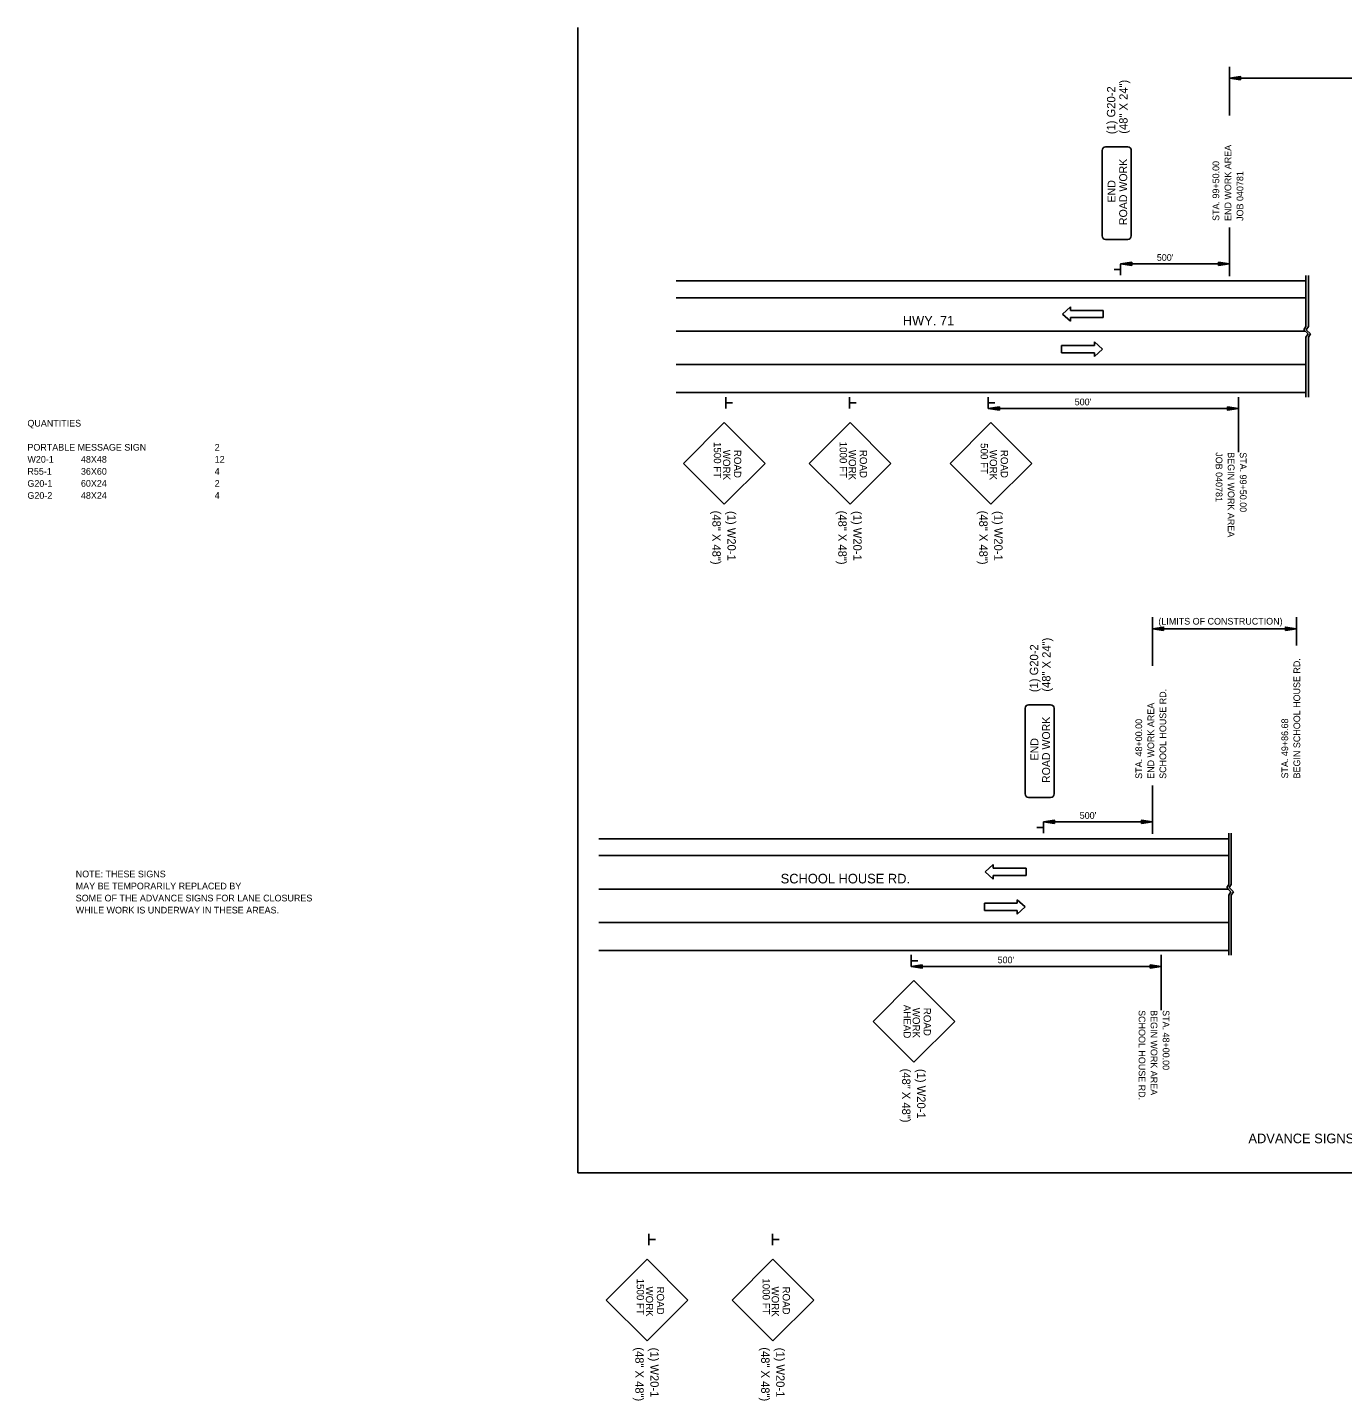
# Model space of a CAD drawing. Extents: x -900 to 1835992, y -12334 to 301063.
# Drawn here: x -900.1 to -428.3, y -12334.1 to -11841.5 of the extents above; entities that cross this region are included whole.
import ezdxf

# ---------------------------------------------------------------- set-up
doc = ezdxf.new("R2010")
doc.units = 0
for name, color, linetype in [('1', 7, 'Continuous'), ('Level 1', 7, 'Continuous'), ('R_MOT', 7, 'Continuous')]:
    doc.layers.add(name, color=color, linetype=linetype)

msp = doc.modelspace()

# ---------------------------------------------------------------- linework, layer by layer
at = {"layer": '1'}
for p, q in [((-468.81, -11873.11), (-468.81, -11855.67)), ((-468.81, -11855.67), (-468.81, -11860.92)), ((-322.23, -11859.76), (-468.81, -11859.76)), ((-468.81, -11930.7), (-468.81, -11913.26)), ((-507.89, -11928.41), (-510.26, -11928.41)), ((-468.81, -11926.36), (-507.89, -11926.36)), ((-507.89, -11926.38), (-507.89, -11930.44)), ((-441.41, -11948.8), (-441.41, -11930.46)), ((-440.54, -11948.8), (-440.54, -11930.46)), ((-667.41, -11932.46), (-441.41, -11932.46)), ((-667.41, -11938.46), (-441.41, -11938.46)), ((-667.41, -11950.46), (-441.67, -11950.46)), ((-441.41, -11948.8), (-442.18, -11949.95)), ((-442.18, -11949.95), (-440.65, -11951.48)), ((-440.54, -11948.8), (-441.31, -11949.95)), ((-441.31, -11949.95), (-439.78, -11951.48)), ((-440.65, -11951.48), (-441.41, -11952.62)), ((-441.41, -11974.2), (-441.41, -11952.62)), ((-439.78, -11951.48), (-440.54, -11952.62)), ((-440.54, -11974.2), (-440.54, -11952.62)), ((-667.41, -11962.46), (-441.41, -11962.46)), ((-667.41, -11972.46), (-441.41, -11972.46)), ((-649.54, -11978.19), (-649.54, -11974.13)), ((-605.14, -11978.19), (-605.14, -11974.13)), ((-555.37, -11978.19), (-555.37, -11974.13)), ((-465.64, -11993.91), (-465.64, -11974.13)), ((-649.54, -11976.16), (-647.17, -11976.16)), ((-605.14, -11976.16), (-602.77, -11976.16)), ((-555.37, -11976.16), (-553, -11976.16)), ((-555.37, -11978.2), (-465.64, -11978.2)), ((-496.43, -12070.57), (-496.43, -12053.13)), ((-496.43, -12053.13), (-496.43, -12058.38)), ((-444.8, -12063.26), (-444.8, -12053.13)), ((-444.8, -12057.22), (-496.43, -12057.22)), ((-496.48, -12130.87), (-496.48, -12113.43)), ((-496.48, -12126.53), (-535.56, -12126.53)), ((-535.56, -12126.54), (-535.56, -12130.61)), ((-695.07, -12132.62), (-469.08, -12132.62)), ((-535.56, -12128.58), (-537.92, -12128.58)), ((-469.08, -12148.96), (-469.08, -12130.62)), ((-468.21, -12148.96), (-468.21, -12130.62)), ((-695.07, -12138.62), (-469.08, -12138.62)), ((-695.07, -12150.62), (-469.33, -12150.62)), ((-469.08, -12148.96), (-469.84, -12150.11)), ((-469.84, -12150.11), (-468.31, -12151.64)), ((-468.31, -12151.64), (-469.08, -12152.79)), ((-469.08, -12174.37), (-469.08, -12152.79)), ((-468.21, -12148.96), (-468.97, -12150.11)), ((-468.97, -12150.11), (-467.44, -12151.64)), ((-467.44, -12151.64), (-468.21, -12152.79)), ((-468.21, -12174.37), (-468.21, -12152.79)), ((-695.07, -12162.62), (-469.08, -12162.62)), ((-695.07, -12172.62), (-469.08, -12172.62)), ((-583.03, -12178.36), (-583.03, -12174.29)), ((-583.03, -12176.33), (-580.67, -12176.33)), ((-493.31, -12194.08), (-493.31, -12174.29)), ((-583.03, -12178.37), (-493.31, -12178.37)), ((-677.2, -12278.36), (-677.2, -12274.29)), ((-632.8, -12278.36), (-632.8, -12274.29)), ((-677.2, -12276.33), (-674.84, -12276.33)), ((-632.8, -12276.33), (-630.44, -12276.33))]:
    msp.add_line(p, q, dxfattribs=at)
for points in [[(-464.85, -11860.36), (-468.81, -11859.76), (-464.85, -11859.16)], [(-503.93, -11926.96), (-507.89, -11926.36), (-503.93, -11925.76)], [(-472.77, -11926.96), (-468.81, -11926.36), (-472.77, -11925.76)], [(-551.41, -11977.6), (-555.37, -11978.2), (-551.41, -11978.8)], [(-469.6, -11977.6), (-465.64, -11978.2), (-469.6, -11978.8)], [(-492.47, -12057.82), (-496.43, -12057.22), (-492.47, -12056.62)], [(-448.76, -12057.82), (-444.8, -12057.22), (-448.76, -12056.62)], [(-531.6, -12127.13), (-535.56, -12126.53), (-531.6, -12125.93)], [(-500.44, -12127.13), (-496.48, -12126.53), (-500.44, -12125.93)], [(-579.07, -12177.77), (-583.03, -12178.37), (-579.07, -12178.97)], [(-497.27, -12177.77), (-493.31, -12178.37), (-497.27, -12178.97)]]:
    msp.add_lwpolyline(points, close=True, dxfattribs=at)
at = {"layer": 'Level 1'}
for p, q in [((-702.63, -12252.44), (-702.63, -11841.52)), ((-62.41, -12252.44), (-702.63, -12252.44))]:
    msp.add_line(p, q, dxfattribs=at)
at = {"layer": 'R_MOT'}
for p, q in [((-514.52, -11885.61), (-514.52, -11916.32)), ((-505.33, -11884.36), (-513.27, -11884.36)), ((-504.08, -11885.61), (-504.08, -11916.32)), ((-505.33, -11917.57), (-513.27, -11917.57)), ((-525.91, -11941.7), (-528.78, -11944.32)), ((-528.78, -11944.32), (-525.91, -11946.93)), ((-525.91, -11943.01), (-525.91, -11941.7)), ((-514.16, -11943.01), (-525.91, -11943.01)), ((-514.16, -11945.62), (-525.91, -11945.62)), ((-525.91, -11945.62), (-525.91, -11946.93)), ((-514.16, -11943.01), (-514.16, -11945.62)), ((-529.06, -11955.59), (-517.3, -11955.59)), ((-529.06, -11955.59), (-529.06, -11958.2)), ((-517.3, -11955.59), (-517.3, -11954.28)), ((-517.3, -11954.28), (-514.43, -11956.89)), ((-529.06, -11958.2), (-517.3, -11958.2)), ((-514.43, -11956.89), (-517.3, -11959.51)), ((-517.3, -11958.2), (-517.3, -11959.51)), ((-664.79, -11997.92), (-650.14, -11983.26)), ((-635.48, -11997.92), (-650.14, -11983.26)), ((-619.64, -11997.92), (-604.99, -11983.26)), ((-590.33, -11997.92), (-604.99, -11983.26)), ((-569.07, -11997.92), (-554.42, -11983.26)), ((-539.76, -11997.92), (-554.42, -11983.26)), ((-650.14, -12012.58), (-664.79, -11997.92)), ((-650.14, -12012.58), (-635.48, -11997.92)), ((-604.99, -12012.58), (-619.64, -11997.92)), ((-604.99, -12012.58), (-590.33, -11997.92)), ((-554.42, -12012.58), (-569.07, -11997.92)), ((-554.42, -12012.58), (-539.76, -11997.92)), ((-542.18, -12085.78), (-542.18, -12116.49)), ((-533, -12084.53), (-540.93, -12084.53)), ((-531.75, -12085.78), (-531.75, -12116.49)), ((-533, -12117.74), (-540.93, -12117.74)), ((-553.58, -12141.86), (-556.45, -12144.48)), ((-553.58, -12143.17), (-553.58, -12141.86)), ((-556.45, -12144.48), (-553.58, -12147.1)), ((-541.82, -12143.17), (-553.58, -12143.17)), ((-541.82, -12145.79), (-553.58, -12145.79)), ((-553.58, -12145.79), (-553.58, -12147.1)), ((-541.82, -12143.17), (-541.82, -12145.79)), ((-556.72, -12155.75), (-544.97, -12155.75)), ((-556.72, -12155.75), (-556.72, -12158.37)), ((-544.97, -12155.75), (-544.97, -12154.44)), ((-544.97, -12154.44), (-542.1, -12157.06)), ((-542.1, -12157.06), (-544.97, -12159.68)), ((-556.72, -12158.37), (-544.97, -12158.37)), ((-544.97, -12158.37), (-544.97, -12159.68)), ((-596.73, -12198.09), (-582.08, -12183.43)), ((-567.42, -12198.09), (-582.08, -12183.43)), ((-582.08, -12212.75), (-596.73, -12198.09)), ((-582.08, -12212.75), (-567.42, -12198.09)), ((-692.46, -12298.09), (-677.81, -12283.43)), ((-663.15, -12298.09), (-677.81, -12283.43)), ((-647.3, -12298.09), (-632.66, -12283.43)), ((-618, -12298.09), (-632.66, -12283.43)), ((-677.81, -12312.75), (-692.46, -12298.09)), ((-677.81, -12312.75), (-663.15, -12298.09)), ((-632.65, -12312.75), (-647.3, -12298.09)), ((-632.65, -12312.75), (-618, -12298.09))]:
    msp.add_line(p, q, dxfattribs=at)
for centre, start, end in [((-513.27, -11885.61), 90.0014, 180.0003), ((-505.33, -11885.61), 0.0003, 90.0014), ((-513.27, -11916.32), 180.0003, 270.0014), ((-505.33, -11916.32), 270.0014, 0.0003), ((-540.93, -12085.78), 90.0014, 180.0003), ((-533, -12085.78), 0.0003, 90.0014), ((-540.93, -12116.49), 180.0003, 270.0014), ((-533, -12116.49), 270.0014, 0.0003)]:
    msp.add_arc(centre, 1.25, start, end, dxfattribs=at)

# ---------------------------------------------------------------- texts
at = {"layer": '1'}
for s, rotation, p in [('END WORK AREA ', 90, (-468.2, -11910.92)), ('STA. 99+50.00', 90, (-472.52, -11910.92)), ('JOB 040781', 90, (-463.88, -11910.92)), ("500'", 360, (-524.38, -11977.08)), ('JOB 040781', 270, (-473.76, -11993.91)), ('BEGIN WORK AREA ', 270, (-469.44, -11993.91)), ('STA. 99+50.00', 270, (-465.12, -11993.91)), ('BEGIN SCHOOL HOUSE RD.', 90, (-443.47, -12110.95)), ('END WORK AREA ', 90, (-495.86, -12111.09)), ('SCHOOL HOUSE RD.', 90, (-491.54, -12111.09)), ('STA. 48+00.00', 90, (-500.18, -12111.09)), ('STA. 49+86.68', 90, (-447.79, -12110.95)), ("500'", 360, (-552.04, -12177.25)), ('SCHOOL HOUSE RD.', 270, (-501.43, -12194.08)), ('BEGIN WORK AREA ', 270, (-497.11, -12194.08)), ('STA. 48+00.00', 270, (-492.79, -12194.08))]:
    msp.add_text(s, height=2.4, rotation=rotation, dxfattribs=at).set_placement(p)
for s, height, p in [("500'", 2.4, (-494.91, -11925.24)), ('HWY. 71', 3.452, (-586.06, -11948.44)), ('QUANTITIES', 2.4, (-900.15, -11984.7)), ('W20-1', 2.4, (-900.15, -11997.66)), ('PORTABLE MESSAGE SIGN', 2.4, (-900.15, -11993.34)), ('48X48', 2.4, (-880.95, -11997.66)), ('2', 2.4, (-832.95, -11993.34)), ('12', 2.4, (-832.95, -11997.66)), ('R55-1', 2.4, (-900.15, -12001.98)), ('36X60', 2.4, (-880.95, -12001.98)), ('4', 2.4, (-832.95, -12001.98)), ('G20-1', 2.4, (-900.15, -12006.3)), ('60X24', 2.4, (-880.95, -12006.3)), ('2', 2.4, (-832.95, -12006.3)), ('G20-2', 2.4, (-900.15, -12010.62)), ('48X24', 2.4, (-880.95, -12010.62)), ('4', 2.4, (-832.95, -12010.62)), ('(LIMITS OF CONSTRUCTION)', 2.4, (-494.36, -12055.75)), ("500'", 2.4, (-522.58, -12125.41)), ('NOTE: THESE SIGNS', 2.4, (-882.81, -12146.43)), ('SCHOOL HOUSE RD.', 3.452, (-629.88, -12148.61)), ('SOME OF THE ADVANCE SIGNS FOR LANE CLOSURES', 2.4, (-882.81, -12155.07)), ('MAY BE TEMPORARILY REPLACED BY', 2.4, (-882.81, -12150.75)), ('WHILE WORK IS UNDERWAY IN THESE AREAS.', 2.4, (-882.81, -12159.39)), ('ADVANCE SIGNS AT BEGINNING AND END OF JOB 040781', 3.452, (-462.04, -12241.82))]:
    msp.add_text(s, height=height, dxfattribs=at).set_placement(p)
at = {"layer": 'R_MOT'}
for s, height, rotation, p in [('(48" X 24")', 3, 89.6927, (-505.43, -11879.65)), ('(1) G20-2', 3, 89.6927, (-509.86, -11879.82)), ('ROAD WORK', 2.835, 90.0006, (-505.56, -11912.41)), ('END', 2.835, 90.0006, (-509.74, -11904.3)), ('1500 FT', 2.613, 270, (-653.86, -11990.23)), ('WORK', 2.613, 270, (-650.59, -11993.04)), ('ROAD', 2.613, 270.0004, (-646.64, -11993.05)), ('1000 FT', 2.613, 270, (-608.71, -11990.13)), ('WORK', 2.613, 270, (-605.44, -11993.04)), ('ROAD', 2.613, 270.0004, (-601.49, -11993.05)), ('500 FT', 2.613, 270, (-558.13, -11990.66)), ('WORK', 2.613, 270, (-554.86, -11993.04)), ('ROAD', 2.613, 270.0004, (-550.92, -11993.05)), ('(48" X 48")', 3, 270, (-654.37, -12014.87)), ('(1) W20-1', 3, 270, (-648.97, -12015)), ('(48" X 48")', 3, 270, (-609.21, -12014.87)), ('(1) W20-1', 3, 270, (-603.82, -12015)), ('(48" X 48")', 3, 270, (-558.64, -12014.87)), ('(1) W20-1', 3, 270, (-553.25, -12015)), ('(1) G20-2', 3, 89.6927, (-537.53, -12079.99)), ('(48" X 24")', 3, 89.6927, (-533.1, -12079.81)), ('ROAD WORK', 2.835, 90.0006, (-533.22, -12112.58)), ('END', 2.835, 90.0006, (-537.41, -12104.47)), ('AHEAD', 2.613, 270, (-585.8, -12192.15)), ('WORK', 2.613, 270, (-582.53, -12193.21)), ('ROAD', 2.613, 270.0004, (-578.58, -12193.22)), ('(48" X 48")', 3, 270, (-586.31, -12215.04)), ('(1) W20-1', 3, 270, (-580.91, -12215.16)), ('1500 FT', 2.613, 270, (-681.52, -12290.4)), ('1000 FT', 2.613, 270, (-636.37, -12290.3)), ('WORK', 2.613, 270, (-678.25, -12293.21)), ('ROAD', 2.613, 270.0004, (-674.31, -12293.22)), ('WORK', 2.613, 270, (-633.1, -12293.21)), ('ROAD', 2.613, 270.0004, (-629.16, -12293.22)), ('(48" X 48")', 3, 270, (-682.03, -12315.04)), ('(1) W20-1', 3, 270, (-676.64, -12315.16)), ('(48" X 48")', 3, 270, (-636.88, -12315.04)), ('(1) W20-1', 3, 270, (-631.48, -12315.16))]:
    msp.add_text(s, height=height, rotation=rotation, dxfattribs=at).set_placement(p)

doc.saveas('drawing.dxf')
